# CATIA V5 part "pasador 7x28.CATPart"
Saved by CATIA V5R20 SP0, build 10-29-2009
Part number: pasador 7x28
Revision: ANY
Definition: UNKNOWN
Nomenclature: pasador 7x28
Source: Unknown
Bounding box of the stored display mesh (mm): x -3.329 to 3.329, y 0 to 28, z -3.5 to 3.5
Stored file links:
  C:\Users\Utente\Desktop\IO LAVORO\3D X SITO CF\CUMSA\3D files SD\SD 4528\pasador 7x28.CATPart
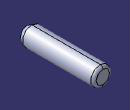
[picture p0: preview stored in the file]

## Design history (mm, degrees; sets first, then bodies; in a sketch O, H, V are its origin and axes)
Body1 "Chaflán1" (main body)
  Solid1: solid without history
